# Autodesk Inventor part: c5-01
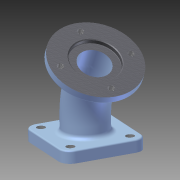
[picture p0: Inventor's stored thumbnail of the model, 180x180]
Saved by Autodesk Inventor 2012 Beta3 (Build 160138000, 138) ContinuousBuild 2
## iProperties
Created: 2010-11
Part Number: c5-01
Material: Cast Iron
Document SubType Name: Modeling
Designer: Beta-8540w
Density: 7.25 g/cm^3
Mass: 2169.78 g
Surface Area: 714.306 cm^2
Volume: 299.28 cm^3
Author: Beta-8540w
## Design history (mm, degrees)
sketch "Sketch1"
  geometry: L1 (50, 50)-(50, -50); L2 (50, -50)-(-50, -50); L3 (-50, -50)-(-50, 50); L4 (-50, 50)-(50, 50); C1 r 28 at (0, 0); C2 r 20 at (0, 0); 2 further points
  constraints: 8 end point, 3 coincident, 2 centre point, 1 horizontal, 9 other
  dimensions: "d0" = 100 distance of L3.end L1.start; "d8" = 8 radial gap between concentric circles of C1 C2; "d17" = 40 diameter of C2
extrude "Extrusion1" new body sketch "Sketch1" distance "d1" = 15; taper "d2" = 0 deg
sketch "Sketch2"
  geometry: L1 (0, 0)-(0, 30); L2 (-13.397, 80)-(-28.397, 105.981); A1 r 100 centre (-100, 30) between (0, 30) and (-13.397, 80)
  constraints: 4 end point, 2 point on circle, 2 tangent, 1 centre point, 1 vertical
  dimensions: "d3" = 30 distance of L1.start L1.end; "d4" = 30 distance of L2.start L2.end; "d5" = 150 deg angle of L1 L2; "d6" = 100 radius of A1
workplane "Work Plane1"
sketch "Sketch3"
  geometry: C1 r 55 at (0, 0); 2 further points
  constraints: 1 centre point, 1 coincident
  dimensions: "d9" = 110 diameter of C1
extrude "Extrusion2" join sketch "Sketch3" distance "d10" = 10; taper "d11" = 0 deg
sweep "Sweep1" dims "d12" = 0
sweep "Sweep2" dims "d13" = 0
fillet "Fillet1" dims "d14" = 14, "d15" = 6, "d16" = 2
hole "Hole1" diameter "d20" = 11; stored, may be unused: countersink angle "d24" = 90 deg, drill point angle "d26" = 118 deg; dims "d18" = 10, "d19" = 10, "d21" = 6, "d22" = 20, "d23" = 2, "d25" = 8
hole "Hole2" diameter "d29" = 11; stored, may be unused: countersink angle "d33" = 90 deg, drill point angle "d35" = 118 deg; dims "d27" = 10, "d28" = 10, "d30" = 6, "d31" = 20, "d32" = 2, "d34" = 8
hole "Hole3" diameter "d38" = 11; stored, may be unused: countersink angle "d42" = 90 deg, drill point angle "d44" = 118 deg; dims "d36" = 10, "d37" = 10, "d39" = 6, "d40" = 20, "d41" = 2, "d43" = 8
hole "Hole4" diameter "d47" = 11; stored, may be unused: countersink angle "d51" = 90 deg, drill point angle "d53" = 118 deg; dims "d45" = 10, "d46" = 10, "d48" = 6, "d49" = 20, "d50" = 2, "d52" = 8
sketch "Sketch4" dims "d54" = 85
  geometry: L1 (0, 42.5)-(42.5, 0); L2 (42.5, 0)-(0, -42.5); L3 (0, -42.5)-(-42.5, 0); L4 (-42.5, 0)-(0, 42.5); C1 r 55 at (0, 0) reference; 3 further points
  constraints: 8 end point, 2 coincident, 1 vertical alignment, 11 other
hole "Hole5" sketch "Sketch4" at (0, 42.5), (42.5, 0), (0, -42.5), (-42.5, 0) diameter "d55" = 8.376; stored, may be unused: countersink angle "d59" = 90 deg, drill point angle "d61" = 118 deg; dims "d56" = 6, "d57" = 20, "d58" = 2, "d60" = 8
sketch "Sketch5"
  geometry: C1 r 55 at (0, 0) reference; C2 r 30 at (0, 0); 1 further point
  constraints: 1 centre point, 1 coincident
  dimensions: "d62" = 60 diameter of C2
extrude "Extrusion3" cut sketch "Sketch5" distance "d63" = 6; taper "d64" = 0 deg
sketch "Sketch6"
  geometry: C1 r 20 at (0, 0) reference; C2 r 30 at (0, 0); C3 r 33 at (0, 0)
  constraints: 2 centre point, 1 coincident
  dimensions: "d65" = 60 diameter of C2; "d66" = 3 radial gap between concentric circles of C3 C2
extrude "Extrusion4" cut sketch "Sketch6" distance "d67" = 3; taper "d68" = 0 deg
fillet "Fillet2" dims "d69" = 0.5
chamfer "Chamfer1" distance "d70" = 2; stored, may be unused: second distance "d71" = 2, angle "d72" = 45 deg
chamfer "Chamfer2" distance "d73" = 1; stored, may be unused: second distance "d74" = 2, angle "d75" = 45 deg
fillet "Fillet3" dims "d76" = 0.5
body "Solid1"
